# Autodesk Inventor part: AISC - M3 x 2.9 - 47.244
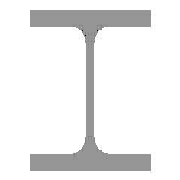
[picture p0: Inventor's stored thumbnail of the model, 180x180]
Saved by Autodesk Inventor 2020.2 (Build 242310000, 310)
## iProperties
Created: 2020-01
Part Number: AISC - M3 x 2.9 - 47.244
Material: Steel, Mild
Description: M-Shape
Document SubType Name: Modeling
Standard: ANSI
Designer: thira
Standards Organization: ANSI
Language: en-US
Size Designation: M3 x 2.9
Categories: <MemberInstance><Categories><Category DisplayName="Structural Shapes" InternalName="089c4875-fa83-4c05-b084-43b9cc11f5ed" Mnemonic="GRDR"><CategoryParameter Dis
Stock Number: M3 x 2.9
Density: 7.85 g/cm^3
Appearance: Semi-Polished
_CCFamilyMember: 14
_CCFamilyDisplayName: ANSI M - M-Shape — Sizes in parentheses have been withdrawn
_FrameMemberDoc: Frame Member File
_Version: 15.0.0
_GetPNFromCC: 1
G_L: 47.244 in
G_W: 2.250 in
G_H: 3.000 in
IsCustomPart: 1
Author: thira
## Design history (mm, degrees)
node "Start Plane"
node "End Plane"
sketch "Sketch"
  geometry: L1 (-28.575, -38.1)-(-28.575, -34.798); L2 (-28.575, -34.798)-(-10.541, -34.798); L3 (-1.143, -25.4)-(-1.143, 0); L4 (-1.143, 0)-(0, 0); L5 (0, 0)-(0, -38.1); L6 (0, -38.1)-(-28.575, -38.1); L7 (-60, 0)-(80, 0); L8 (0, -60)-(0, 80); L9 (28.575, -38.1)-(28.575, -34.798); L10 (28.575, -34.798)-(10.541, -34.798); L11 (0, -38.1)-(28.575, -38.1); L12 (1.143, -25.4)-(1.143, 0); L13 (1.143, 0)-(0, 0); L14 (-28.575, 38.1)-(-28.575, 34.798); L15 (0, 38.1)-(-28.575, 38.1); L16 (0, 38.1)-(28.575, 38.1); L17 (28.575, 34.798)-(10.541, 34.798); L18 (-28.575, 34.798)-(-10.541, 34.798); L19 (1.143, 25.4)-(1.143, 0); L20 (-1.143, 25.4)-(-1.143, 0); L21 (28.575, 38.1)-(28.575, 34.798); L22 (0, 108)-(0, -88) reference; L23 (-88, 0)-(108, 0) reference; A1 r 9.398 centre (-10.541, 25.4) between (-1.143, 25.4) and (-10.541, 34.798); A2 r 9.398 centre (10.541, 25.4) between (10.541, 34.798) and (1.143, 25.4); A3 r 9.398 centre (10.541, -25.4) between (1.143, -25.4) and (10.541, -34.798); A4 r 9.398 centre (-10.541, -25.4) between (-10.541, -34.798) and (-1.143, -25.4); 4 further points
  constraints: 42 end point, 11 symmetric about line, 8 point on circle, 8 point on line, 8 tangent, 4 centre point, 4 collinear, 4 parallel, 3 equal radius, 1 perpendicular, 1 vertical, 13 other
  dimensions: "d1" = 38.1 vertical distance of L1.start L3.end (= 0.5 x G_H); "d2" = 3.302 distance between parallel lines of L2 L6 (= G_T1); "d3" = 28.575 distance from line of L5.end L1 (= 0.5 x G_W); "d4" = 1.143 distance between parallel lines of L5 L3 (= 0.5 x G_T); "d13" = 9.398 radius of A1 (= G_IR)
extrude "Body" new body sketch "Sketch" stored distance "d5" = 1200 (= G_L); taper "d6" = 0 deg
node "Driven Length"
  sketch "Sketch4"
    geometry: L1 (0, 0)-(10, 0) reference
    constraints: 2 end point, 1 horizontal
  workplane "Work Plane3"
  sketch "Sketch5"
    geometry: L1 (-2, 0)-(12, 0) reference; L2 (-2, 1200)-(12, 1200) reference
    dimensions: "d15" = 1200 distance between parallel lines of L1 L2 (derived)
body "Solid1"
other parameters: "G_W" = 57.15 [user parameter; used in 1 equation term], "G_H" = 76.2 [user parameter; used in 1 equation term], "G_T" = 2.286 [user parameter; used in 1 equation term], "G_T1" = 3.302 [user parameter; used in 1 equation term], "G_IR" = 9.398 [user parameter; used in 1 equation term], "G_L" = 1200 (= d15) [user parameter; used in 1 equation term], "G_OFFSET_START" = 0 [user parameter; used in 1 equation term], "G_OFFSET_END" = 0 [user parameter; used in 1 equation term], "d11" = 0 (computed from G_OFFSET_START), "d12" = 1200 (= G_OFFSET_END + B_L), "B_L" = 1200 [user parameter; used in 1 equation term], "d14" = 90 deg
